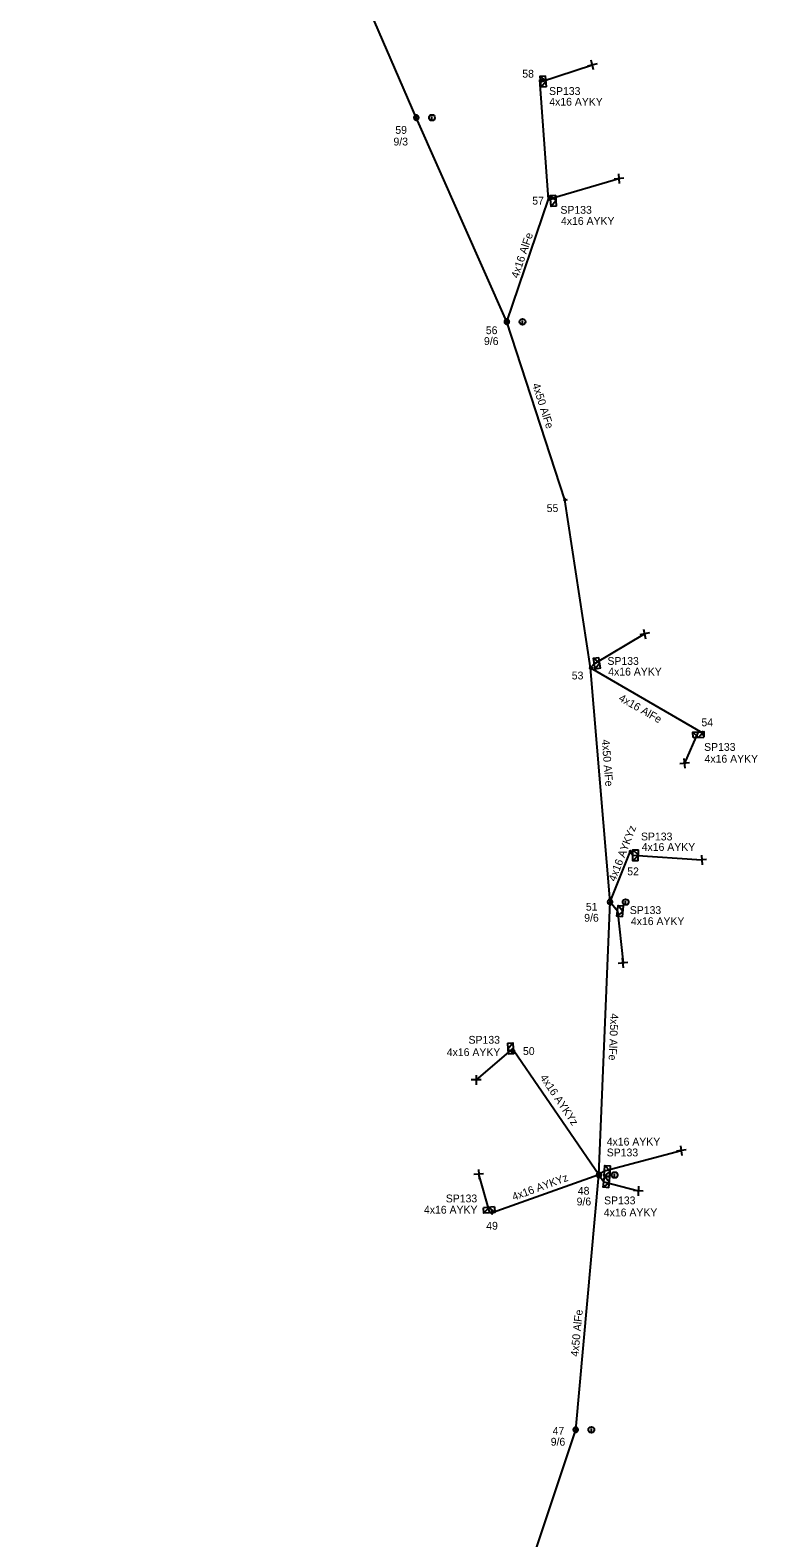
# Model space of a CAD drawing. Extents: x -748492 to -735633, y -1146251 to -1139940.
# Drawn here: x -745655.9 to -745562.8, y -1143479.1 to -1143286.4 of the extents above; entities that cross this region are included whole.
import ezdxf

# ---------------------------------------------------------------- set-up
doc = ezdxf.new("R2010")
doc.units = 0
for name, color, linetype in [('Vrstva 1', 7, 'Continuous'), ('Vrstva 10', 7, 'Continuous'), ('Vrstva 12', 7, 'Continuous'), ('Vrstva 13', 7, 'Continuous'), ('Vrstva 14', 7, 'Continuous'), ('Vrstva 2', 7, 'Continuous'), ('Vrstva 31', 7, 'Continuous'), ('Vrstva 33', 7, 'Continuous'), ('Vrstva 34', 7, 'Continuous'), ('Vrstva 36', 7, 'Continuous'), ('Vrstva 52', 7, 'Continuous'), ('Vrstva 53', 7, 'Continuous'), ('Vrstva 54', 7, 'Continuous'), ('Vrstva 59', 7, 'Continuous'), ('Vrstva 9', 7, 'Continuous')]:
    doc.layers.add(name, color=color, linetype=linetype)

# ---------------------------------------------------------------- blocks, each defined once
blk = doc.blocks.new('NN440')
at = {"layer": 'Vrstva 2'}
for points in [[(0.63, 0), (0.63, 0.06), (0.62, 0.13), (0.6, 0.19), (0.58, 0.25), (0.55, 0.31), (0.51, 0.37), (0.47, 0.42), (0.42, 0.46), (0.37, 0.51), (0.32, 0.54), (0.26, 0.57), (0.2, 0.59), (0.13, 0.61), (0.07, 0.62), (0, 0.63), (-0.06, 0.62), (-0.13, 0.61), (-0.19, 0.59), (-0.26, 0.57), (-0.31, 0.54), (-0.37, 0.51), (-0.42, 0.46), (-0.47, 0.42), (-0.51, 0.37), (-0.54, 0.31), (-0.57, 0.25), (-0.6, 0.19), (-0.62, 0.13), (-0.63, 0.06), (-0.63, 0), (-0.63, -0.07), (-0.62, -0.14), (-0.6, -0.2), (-0.57, -0.26), (-0.54, -0.32), (-0.51, -0.37), (-0.47, -0.43), (-0.42, -0.47), (-0.37, -0.51), (-0.31, -0.55), (-0.26, -0.58), (-0.19, -0.6), (-0.13, -0.62), (-0.06, -0.63), (0, -0.63), (0.07, -0.63), (0.13, -0.62), (0.2, -0.6), (0.26, -0.58), (0.32, -0.55), (0.37, -0.51), (0.42, -0.47), (0.47, -0.43), (0.51, -0.37), (0.55, -0.32), (0.58, -0.26), (0.6, -0.2), (0.62, -0.14), (0.63, -0.07), (0.63, 0)], [(-0.63, 0), (0.63, 0)], [(-0.6, -0.18), (0.57, -0.18)], [(-0.51, -0.32), (0.5, -0.32)], [(-0.37, -0.47), (0.35, -0.47)]]:
    blk.add_lwpolyline(points, dxfattribs=at)
blk = doc.blocks.new('NN770')
at = {"layer": 'Vrstva 10'}
for p, q in [((0, 0.19), (0, 0.26)), ((0, -0.28), (0, 0.11))]:
    blk.add_line(p, q, dxfattribs=at)
blk.add_circle((0, -0.01), 0.375, dxfattribs=at)
blk = doc.blocks.new('NN800')
at = {"layer": 'Vrstva 1'}
for points in [[(-0.44, 0.44), (0.44, -0.44)], [(-0.44, -0.44), (0.44, 0.44)]]:
    blk.add_lwpolyline(points, dxfattribs=at)
blk = doc.blocks.new('NN630')
at = {"layer": 'Vrstva 9'}
for points in [[(0, -0.7), (-0.7, 0)], [(-0.7, -0.7), (-0.7, 0), (0.7, 0), (0.7, -0.7)], [(-0.7, -0.7), (0.7, -0.7)], [(0, -0.7), (0.7, 0)]]:
    blk.add_lwpolyline(points, dxfattribs=at)
blk = doc.blocks.new('NN500')
at = {"layer": 'Vrstva 2'}
for points in [[(0, -0.24), (0.02, -0.23), (0.05, -0.23), (0.07, -0.22), (0.09, -0.22), (0.12, -0.2), (0.14, -0.19), (0.16, -0.18), (0.17, -0.16), (0.19, -0.14), (0.2, -0.12), (0.21, -0.1), (0.22, -0.07), (0.23, -0.05), (0.23, -0.02), (0.23, 0), (0.23, 0.02), (0.23, 0.05), (0.22, 0.07), (0.21, 0.1), (0.2, 0.12), (0.19, 0.14), (0.17, 0.16), (0.16, 0.17), (0.14, 0.19), (0.12, 0.2), (0.09, 0.21), (0.07, 0.22), (0.05, 0.23), (0.02, 0.23), (0, 0.23), (-0.03, 0.23), (-0.05, 0.23), (-0.07, 0.22), (-0.1, 0.21), (-0.12, 0.2), (-0.14, 0.19), (-0.16, 0.17), (-0.18, 0.16), (-0.19, 0.14), (-0.2, 0.12), (-0.22, 0.1), (-0.22, 0.07), (-0.23, 0.05), (-0.23, 0.02), (-0.24, 0), (-0.23, -0.02), (-0.23, -0.05), (-0.22, -0.07), (-0.22, -0.1), (-0.2, -0.12), (-0.19, -0.14), (-0.18, -0.16), (-0.16, -0.18), (-0.14, -0.19), (-0.12, -0.2), (-0.1, -0.22), (-0.07, -0.22), (-0.05, -0.23), (-0.03, -0.23), (0, -0.24)], [(0, -0.24), (0.02, -0.23), (0.05, -0.23), (0.07, -0.22), (0.09, -0.22), (0.12, -0.2), (0.14, -0.19), (0.16, -0.18), (0.17, -0.16), (0.19, -0.14), (0.2, -0.12), (0.21, -0.1), (0.22, -0.07), (0.23, -0.05), (0.23, -0.02), (0.23, 0), (0.23, 0.02), (0.23, 0.05), (0.22, 0.07), (0.21, 0.1), (0.2, 0.12), (0.19, 0.14), (0.17, 0.16), (0.16, 0.17), (0.14, 0.19), (0.12, 0.2), (0.09, 0.21), (0.07, 0.22), (0.05, 0.23), (0.02, 0.23), (0, 0.23), (-0.03, 0.23), (-0.05, 0.23), (-0.07, 0.22), (-0.1, 0.21), (-0.12, 0.2), (-0.14, 0.19), (-0.16, 0.17), (-0.18, 0.16), (-0.19, 0.14), (-0.2, 0.12), (-0.22, 0.1), (-0.22, 0.07), (-0.23, 0.05), (-0.23, 0.02), (-0.24, 0), (-0.23, -0.02), (-0.23, -0.05), (-0.22, -0.07), (-0.22, -0.1), (-0.2, -0.12), (-0.19, -0.14), (-0.18, -0.16), (-0.16, -0.18), (-0.14, -0.19), (-0.12, -0.2), (-0.1, -0.22), (-0.07, -0.22), (-0.05, -0.23), (-0.03, -0.23), (0, -0.24)], [(0, -0.21), (0.02, -0.2), (0.04, -0.2), (0.06, -0.2), (0.08, -0.19), (0.1, -0.18), (0.12, -0.17), (0.14, -0.15), (0.15, -0.14), (0.16, -0.12), (0.18, -0.1), (0.19, -0.08), (0.19, -0.06), (0.2, -0.04), (0.2, -0.02), (0.2, 0), (0.2, 0.02), (0.2, 0.04), (0.19, 0.06), (0.19, 0.08), (0.18, 0.1), (0.16, 0.12), (0.15, 0.14), (0.14, 0.15), (0.12, 0.17), (0.1, 0.18), (0.08, 0.19), (0.06, 0.19), (0.04, 0.2), (0.02, 0.2), (0, 0.2), (-0.02, 0.2), (-0.04, 0.2), (-0.06, 0.19), (-0.08, 0.19), (-0.1, 0.18), (-0.12, 0.17), (-0.14, 0.15), (-0.15, 0.14), (-0.17, 0.12), (-0.18, 0.1), (-0.19, 0.08), (-0.2, 0.06), (-0.2, 0.04), (-0.21, 0.02), (-0.21, 0), (-0.21, -0.02), (-0.2, -0.04), (-0.2, -0.06), (-0.19, -0.08), (-0.18, -0.1), (-0.17, -0.12), (-0.15, -0.14), (-0.14, -0.15), (-0.12, -0.17), (-0.1, -0.18), (-0.08, -0.19), (-0.06, -0.2), (-0.04, -0.2), (-0.02, -0.2), (0, -0.21)], [(0, -0.18), (0.02, -0.18), (0.04, -0.17), (0.05, -0.17), (0.07, -0.16), (0.09, -0.15), (0.1, -0.14), (0.12, -0.13), (0.13, -0.12), (0.14, -0.1), (0.15, -0.09), (0.16, -0.07), (0.17, -0.05), (0.17, -0.04), (0.17, -0.02), (0.17, 0), (0.17, 0.02), (0.17, 0.04), (0.17, 0.05), (0.16, 0.07), (0.15, 0.09), (0.14, 0.1), (0.13, 0.12), (0.12, 0.13), (0.1, 0.14), (0.09, 0.15), (0.07, 0.16), (0.05, 0.17), (0.04, 0.17), (0.02, 0.17), (0, 0.18), (-0.02, 0.17), (-0.04, 0.17), (-0.06, 0.17), (-0.07, 0.16), (-0.09, 0.15), (-0.1, 0.14), (-0.12, 0.13), (-0.13, 0.12), (-0.14, 0.1), (-0.15, 0.09), (-0.16, 0.07), (-0.17, 0.05), (-0.17, 0.04), (-0.18, 0.02), (-0.18, 0), (-0.18, -0.02), (-0.17, -0.04), (-0.17, -0.05), (-0.16, -0.07), (-0.15, -0.09), (-0.14, -0.1), (-0.13, -0.12), (-0.12, -0.13), (-0.1, -0.14), (-0.09, -0.15), (-0.07, -0.16), (-0.06, -0.17), (-0.04, -0.17), (-0.02, -0.18), (0, -0.18)], [(0, -0.15), (0.01, -0.15), (0.03, -0.14), (0.04, -0.14), (0.06, -0.13), (0.07, -0.13), (0.08, -0.12), (0.1, -0.11), (0.11, -0.1), (0.12, -0.09), (0.13, -0.07), (0.13, -0.06), (0.14, -0.05), (0.14, -0.03), (0.14, -0.02), (0.14, 0), (0.14, 0.01), (0.14, 0.03), (0.14, 0.04), (0.13, 0.06), (0.13, 0.07), (0.12, 0.09), (0.11, 0.1), (0.1, 0.11), (0.08, 0.12), (0.07, 0.13), (0.06, 0.13), (0.04, 0.14), (0.03, 0.14), (0.01, 0.14), (0, 0.15), (-0.02, 0.14), (-0.03, 0.14), (-0.05, 0.14), (-0.06, 0.13), (-0.07, 0.13), (-0.09, 0.12), (-0.1, 0.11), (-0.11, 0.1), (-0.12, 0.09), (-0.13, 0.07), (-0.13, 0.06), (-0.14, 0.04), (-0.14, 0.03), (-0.15, 0.01), (-0.15, 0), (-0.15, -0.02), (-0.14, -0.03), (-0.14, -0.05), (-0.13, -0.06), (-0.13, -0.07), (-0.12, -0.09), (-0.11, -0.1), (-0.1, -0.11), (-0.09, -0.12), (-0.07, -0.13), (-0.06, -0.13), (-0.05, -0.14), (-0.03, -0.14), (-0.02, -0.15), (0, -0.15)], [(0, -0.12), (0.01, -0.12), (0.02, -0.11), (0.03, -0.11), (0.05, -0.11), (0.06, -0.1), (0.07, -0.09), (0.08, -0.09), (0.09, -0.08), (0.09, -0.07), (0.1, -0.06), (0.11, -0.05), (0.11, -0.04), (0.11, -0.02), (0.11, -0.01), (0.12, 0), (0.11, 0.01), (0.11, 0.02), (0.11, 0.04), (0.11, 0.05), (0.1, 0.06), (0.09, 0.07), (0.09, 0.08), (0.08, 0.09), (0.07, 0.09), (0.06, 0.1), (0.05, 0.11), (0.03, 0.11), (0.02, 0.11), (0.01, 0.12), (0, 0.12), (-0.01, 0.12), (-0.03, 0.11), (-0.04, 0.11), (-0.05, 0.11), (-0.06, 0.1), (-0.07, 0.09), (-0.08, 0.09), (-0.09, 0.08), (-0.1, 0.07), (-0.1, 0.06), (-0.11, 0.05), (-0.11, 0.04), (-0.12, 0.02), (-0.12, 0.01), (-0.12, 0), (-0.12, -0.01), (-0.12, -0.02), (-0.11, -0.04), (-0.11, -0.05), (-0.1, -0.06), (-0.1, -0.07), (-0.09, -0.08), (-0.08, -0.09), (-0.07, -0.09), (-0.06, -0.1), (-0.05, -0.11), (-0.04, -0.11), (-0.03, -0.11), (-0.01, -0.12), (0, -0.12)], [(0, -0.09), (0.01, -0.09), (0.02, -0.09), (0.03, -0.08), (0.03, -0.08), (0.04, -0.08), (0.05, -0.07), (0.06, -0.07), (0.06, -0.06), (0.07, -0.05), (0.07, -0.04), (0.08, -0.04), (0.08, -0.03), (0.08, -0.02), (0.09, -0.01), (0.09, 0), (0.09, 0.01), (0.08, 0.02), (0.08, 0.03), (0.08, 0.03), (0.07, 0.04), (0.07, 0.05), (0.06, 0.06), (0.06, 0.06), (0.05, 0.07), (0.04, 0.07), (0.03, 0.08), (0.03, 0.08), (0.02, 0.08), (0.01, 0.09), (0, 0.09), (-0.01, 0.09), (-0.02, 0.08), (-0.03, 0.08), (-0.04, 0.08), (-0.04, 0.07), (-0.05, 0.07), (-0.06, 0.06), (-0.07, 0.06), (-0.07, 0.05), (-0.08, 0.04), (-0.08, 0.03), (-0.08, 0.03), (-0.09, 0.02), (-0.09, 0.01), (-0.09, 0), (-0.09, -0.01), (-0.09, -0.02), (-0.08, -0.03), (-0.08, -0.04), (-0.08, -0.04), (-0.07, -0.05), (-0.07, -0.06), (-0.06, -0.07), (-0.05, -0.07), (-0.04, -0.08), (-0.04, -0.08), (-0.03, -0.08), (-0.02, -0.09), (-0.01, -0.09), (0, -0.09)], [(0, -0.06), (0, -0.06), (0.01, -0.06), (0.02, -0.05), (0.02, -0.05), (0.03, -0.05), (0.03, -0.05), (0.04, -0.04), (0.04, -0.04), (0.05, -0.03), (0.05, -0.03), (0.05, -0.02), (0.05, -0.02), (0.05, -0.01), (0.06, -0.01), (0.06, 0), (0.06, 0.01), (0.05, 0.01), (0.05, 0.02), (0.05, 0.02), (0.05, 0.03), (0.05, 0.03), (0.04, 0.04), (0.04, 0.04), (0.03, 0.05), (0.03, 0.05), (0.02, 0.05), (0.02, 0.05), (0.01, 0.06), (0, 0.06), (0, 0.06), (-0.01, 0.06), (-0.01, 0.06), (-0.02, 0.05), (-0.02, 0.05), (-0.03, 0.05), (-0.03, 0.05), (-0.04, 0.04), (-0.04, 0.04), (-0.05, 0.03), (-0.05, 0.03), (-0.05, 0.02), (-0.06, 0.02), (-0.06, 0.01), (-0.06, 0.01), (-0.06, 0), (-0.06, -0.01), (-0.06, -0.01), (-0.06, -0.02), (-0.05, -0.02), (-0.05, -0.03), (-0.05, -0.03), (-0.04, -0.04), (-0.04, -0.04), (-0.03, -0.05), (-0.03, -0.05), (-0.02, -0.05), (-0.02, -0.05), (-0.01, -0.06), (-0.01, -0.06), (0, -0.06)], [(0, -0.03), (0, -0.03), (0, -0.03), (0.01, -0.03), (0.01, -0.03), (0.01, -0.02), (0.02, -0.02), (0.02, -0.02), (0.02, -0.02), (0.02, -0.02), (0.02, -0.01), (0.02, -0.01), (0.03, -0.01), (0.03, -0.01), (0.03, 0), (0.03, 0), (0.03, 0), (0.03, 0.01), (0.03, 0.01), (0.02, 0.01), (0.02, 0.01), (0.02, 0.02), (0.02, 0.02), (0.02, 0.02), (0.02, 0.02), (0.01, 0.02), (0.01, 0.02), (0.01, 0.03), (0, 0.03), (0, 0.03), (0, 0.03), (0, 0.03), (-0.01, 0.03), (-0.01, 0.03), (-0.01, 0.02), (-0.02, 0.02), (-0.02, 0.02), (-0.02, 0.02), (-0.02, 0.02), (-0.02, 0.02), (-0.03, 0.01), (-0.03, 0.01), (-0.03, 0.01), (-0.03, 0.01), (-0.03, 0), (-0.03, 0), (-0.03, 0), (-0.03, -0.01), (-0.03, -0.01), (-0.03, -0.01), (-0.03, -0.01), (-0.02, -0.02), (-0.02, -0.02), (-0.02, -0.02), (-0.02, -0.02), (-0.02, -0.02), (-0.01, -0.03), (-0.01, -0.03), (-0.01, -0.03), (0, -0.03), (0, -0.03)], [(0.23, 0), (0.7, 0)]]:
    blk.add_lwpolyline(points, dxfattribs=at)
blk = doc.blocks.new('NN510')
at = {"layer": 'Vrstva 2'}
blk.add_lwpolyline([(0, 0), (0, 0.94)], dxfattribs=at)

msp = doc.modelspace()

# ---------------------------------------------------------------- linework, layer by layer
at = {"layer": 'Vrstva 1'}
for points in [[(-745594.9, -1143323.68), (-745606.48, -1143297.59), (-745617.77, -1143271.59), (-745636.81, -1143247.63), (-745655.86, -1143223.12)], [(-745594.9, -1143323.68), (-745589.57, -1143308.03), (-745590.68, -1143292.76)], [(-745584.2, -1143367.93), (-745587.48, -1143346.45), (-745594.9, -1143323.68)], [(-745581.71, -1143397.86), (-745584.2, -1143367.93)], [(-745584.2, -1143367.93), (-745569.9, -1143376.24)], [(-745583.12, -1143432.75), (-745581.71, -1143397.86)], [(-745596.14, -1143495.57), (-745586.1, -1143465.32), (-745583.12, -1143432.75)]]:
    msp.add_lwpolyline(points, dxfattribs=at)
at = {"layer": 'Vrstva 52'}
for points in [[(-745590.68, -1143292.76), (-745590.59, -1143293)], [(-745589.57, -1143308.03), (-745589.3, -1143308.24)], [(-745584.2, -1143367.93), (-745583.72, -1143367.4)], [(-745569.9, -1143376.24), (-745570.43, -1143376.12)], [(-745581.71, -1143397.86), (-745579.12, -1143391.45)], [(-745579.12, -1143391.45), (-745578.79, -1143391.88)], [(-745581.71, -1143397.86), (-745580.75, -1143398.99)], [(-745594.03, -1143416.9), (-745594.1, -1143416.56)], [(-745583.12, -1143432.75), (-745594.03, -1143416.9)], [(-745583.12, -1143432.75), (-745596.8, -1143437.59)], [(-745583.12, -1143432.75), (-745582.41, -1143432.23)], [(-745583.12, -1143432.75), (-745582.49, -1143433.63)], [(-745596.8, -1143437.59), (-745597.1, -1143437.59)]]:
    msp.add_lwpolyline(points, dxfattribs=at)
at = {"layer": 'Vrstva 59'}
for points in [[(-745590.59, -1143293), (-745583.97, -1143290.86)], [(-745589.57, -1143308.03), (-745580.58, -1143305.39)], [(-745583.72, -1143367.4), (-745577.29, -1143363.59)], [(-745570.43, -1143376.12), (-745572.17, -1143380.13)], [(-745578.79, -1143391.88), (-745569.98, -1143392.48)], [(-745580.75, -1143398.99), (-745580.04, -1143405.66)], [(-745594.1, -1143416.56), (-745598.83, -1143420.61)], [(-745582.41, -1143432.23), (-745572.6, -1143429.64)], [(-745597.1, -1143437.59), (-745598.49, -1143432.66)], [(-745582.49, -1143433.63), (-745578.09, -1143434.8)]]:
    msp.add_lwpolyline(points, dxfattribs=at)

# ---------------------------------------------------------------- block references
at = {"layer": 'Vrstva 13'}
for p, rotation in [((-745590.68, -1143292.76), -90), ((-745589.57, -1143308.03), -83.87987218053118)]:
    msp.add_blockref('NN510', p, dxfattribs=dict(at, rotation=rotation))
for name, p, xscale, yscale, rotation in [('NN440', (-745606.48, -1143297.59), 0.5, 0.5, -67.98267507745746), ('NN440', (-745594.9, -1143323.68), 0.5000000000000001, 0.4999999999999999, 102.54703891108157), ('NN500', (-745587.48, -1143346.45), 0.5000000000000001, 0.5, 4.512999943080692), ('NN500', (-745584.2, -1143367.93), 0.5000000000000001, 0.4999999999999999, 3.609000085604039), ('NN500', (-745569.9, -1143376.24), 0.49999999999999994, 0.5000000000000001, -85.11000004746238), ('NN500', (-745579.12, -1143391.45), 0.5, 0.5000000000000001, -0.7939999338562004), ('NN440', (-745581.71, -1143397.86), 0.4999999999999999, 0.5000000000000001, 88.72696943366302), ('NN500', (-745594.03, -1143416.9), 0.5000000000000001, 0.4999999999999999, -175.20300013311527), ('NN440', (-745583.12, -1143432.75), 0.49999999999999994, 0.5000000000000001, 87.84049996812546), ('NN500', (-745596.8, -1143437.59), 0.5000000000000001, 0.5, 97.08099998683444), ('NN440', (-745586.1, -1143465.32), 0.5, 0.49999999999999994, 72.95900270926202)]:
    msp.add_blockref(name, p, dxfattribs=dict(at, xscale=xscale, yscale=yscale, rotation=rotation))
at = {"layer": 'Vrstva 31'}
for p, rotation in [((-745590.59, -1143293), 94.44730555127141), ((-745589.3, -1143308.24), 93.9695088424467), ((-745583.72, -1143367.4), 98.67707219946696), ((-745570.43, -1143376.12), 2.8335582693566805), ((-745578.79, -1143391.88), 89.69812329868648), ((-745580.75, -1143398.99), 84.03762121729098), ((-745594.09, -1143416.57), -86.46633888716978), ((-745582.49, -1143433.63), 83.59601877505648), ((-745582.41, -1143432.23), 86.5566684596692), ((-745597.15, -1143437.6), -175.87349050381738)]:
    msp.add_blockref('NN630', p, dxfattribs=dict(at, rotation=rotation))
at = {"layer": 'Vrstva 34'}
for p, rotation in [((-745583.97, -1143290.86), 147.8665304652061), ((-745580.58, -1143305.39), -130.2028305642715), ((-745577.29, -1143363.59), -123.9908722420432), ((-745572.17, -1143380.13), 141.85467214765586), ((-745569.98, -1143392.48), -131.40877780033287), ((-745580.04, -1143405.66), 140.5954804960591), ((-745598.83, -1143420.61), -135.06961671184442), ((-745572.6, -1143429.64), -127.37245561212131), ((-745598.49, -1143432.66), -131.53372218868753), ((-745578.09, -1143434.8), -138.5606000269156)]:
    msp.add_blockref('NN800', p, dxfattribs=dict(at, rotation=rotation))
at = {"layer": 'Vrstva 36'}
for p in [(-745604.48, -1143297.59), (-745592.9, -1143323.68), (-745579.71, -1143397.86), (-745581.12, -1143432.75), (-745584.1, -1143465.32)]:
    msp.add_blockref('NN770', p, dxfattribs=at)

# ---------------------------------------------------------------- texts
at = {"layer": 'Vrstva 12'}
for s, p in [('9/3', (-745609.4, -1143301.15)), ('9/6', (-745597.83, -1143326.66)), ('9/6', (-745585.01, -1143400.38)), ('9/6', (-745585.98, -1143436.65)), ('9/6', (-745589.29, -1143467.36))]:
    msp.add_text(s, height=1, dxfattribs=at).set_placement(p)
at = {"layer": 'Vrstva 14'}
for s, p in [('58', (-745592.93, -1143292.48)), ('59', (-745609.16, -1143299.66)), ('57', (-745591.66, -1143308.71)), ('56', (-745597.59, -1143325.27)), ('55', (-745589.81, -1143348.01)), ('53', (-745586.6, -1143369.41)), ('54', (-745570.02, -1143375.4)), ('52', (-745579.51, -1143394.45)), ('51', (-745584.8, -1143398.97)), ('50', (-745592.84, -1143417.42)), ('48', (-745585.83, -1143435.28)), ('49', (-745597.54, -1143439.75)), ('47', (-745589.05, -1143465.97))]:
    msp.add_text(s, height=1, dxfattribs=at).set_placement(p)
at = {"layer": 'Vrstva 2'}
for s, rotation, p in [('4x16 AlFe', 71.438, (-745593.45, -1143318.2)), ('4x50 AlFe', 287.833, (-745591.67, -1143331.71)), ('4x16 AlFe', 330.327, (-745580.69, -1143372.07)), ('4x50 AlFe', 274.512, (-745582.77, -1143377.12)), ('4x50 AlFe', 267.672, (-745581.64, -1143412.08)), ('4x50 AlFe', 84.428, (-745585.77, -1143456.01))]:
    msp.add_text(s, height=1, rotation=rotation, dxfattribs=at).set_placement(p)
at = {"layer": 'Vrstva 33'}
for p in [(-745589.51, -1143294.69), (-745588.05, -1143309.88), (-745582.04, -1143367.55), (-745569.68, -1143378.54), (-745577.75, -1143389.99), (-745579.18, -1143399.4), (-745599.8, -1143415.98), (-745582.13, -1143430.38), (-745602.71, -1143436.26), (-745582.47, -1143436.51)]:
    msp.add_text('SP133', height=1, dxfattribs=at).set_placement(p)
at = {"layer": 'Vrstva 53'}
for rotation, p in [(68.998, (-745581.03, -1143395.32)), (304.01, (-745590.71, -1143420.32)), (20.1, (-745594.02, -1143436.05))]:
    msp.add_text('4x16 AYKYz', height=1, rotation=rotation, dxfattribs=at).set_placement(p)
at = {"layer": 'Vrstva 54'}
for rotation, p in [(359.951, (-745589.48, -1143296.06)), (0.062, (-745587.98, -1143311.3)), (359.959, (-745581.94, -1143368.91)), (359.955, (-745569.62, -1143380.05)), (359.954, (-745579.04, -1143400.81)), (0.042, (-745602.58, -1143417.56)), (0.035, (-745582.13, -1143429)), (0.04, (-745605.5, -1143437.7)), (0.287, (-745582.5, -1143438.06))]:
    msp.add_text('4x16 AYKY', height=1, rotation=rotation, dxfattribs=at).set_placement(p)
msp.add_text('4x16 AYKY', height=1, dxfattribs=at).set_placement((-745577.66, -1143391.33))

doc.saveas('drawing.dxf')
